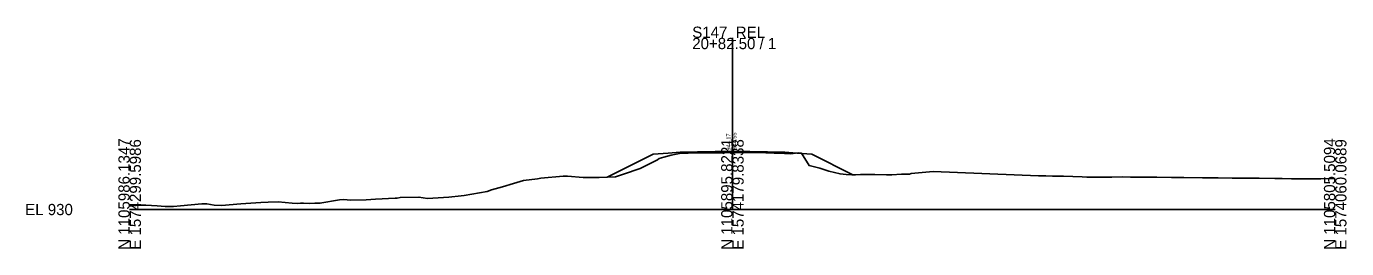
# Model space of a CAD drawing. Extents: x 1557985 to 1558314, y 1113650 to 1118205.
# Drawn here: x 1557985.4 to 1558314, y 1118150.1 to 1118205.3 of the extents above; entities that cross this region are included whole.
import ezdxf

# ---------------------------------------------------------------- set-up
doc = ezdxf.new("R2010")
doc.units = 0
for name, color, linetype in [('RD_GPK_XS_Cell', 7, 'Continuous'), ('RD_XS_EarthShd', 7, 'Continuous'), ('RD_XS_ExGround', 7, 'Continuous'), ('RD_XS_Pave', 7, 'Continuous'), ('RD_XS_TieSlope', 7, 'Continuous'), ('RD_XS_TX_Elev_EX', 7, 'Continuous'), ('RD_XS_TX_Elev_PR', 7, 'Continuous')]:
    doc.layers.add(name, color=color, linetype=linetype)

msp = doc.modelspace()

# ---------------------------------------------------------------- linework, layer by layer
at = {"layer": 'RD_GPK_XS_Cell'}
for p, q in [((1558161.13, 1118159.8), (1558161.13, 1118202.45)), ((1558011.13, 1118159.8), (1558161.13, 1118159.8)), ((1558161.13, 1118159.8), (1558311.13, 1118159.8))]:
    msp.add_line(p, q, dxfattribs=at)
at = {"layer": 'RD_XS_EarthShd'}
for p, q in [((1558145.13, 1118173.84), (1558141.38, 1118173.54)), ((1558148.13, 1118174.08), (1558145.13, 1118173.84)), ((1558174.13, 1118174.08), (1558177.13, 1118173.84)), ((1558177.13, 1118173.84), (1558180.88, 1118173.54))]:
    msp.add_line(p, q, dxfattribs=at)
at = {"layer": 'RD_XS_ExGround'}
msp.add_lwpolyline([(1558011.13, 1118160.72), (1558011.7, 1118160.75), (1558013.86, 1118160.91), (1558015.19, 1118160.85), (1558017.94, 1118160.7), (1558019.97, 1118160.57), (1558022.04, 1118160.58), (1558023.79, 1118160.74), (1558029.11, 1118161.19), (1558029.98, 1118161.25), (1558030.37, 1118161.18), (1558032.19, 1118160.86), (1558033.97, 1118160.79), (1558038.76, 1118161.2), (1558043.74, 1118161.54), (1558045.63, 1118161.6), (1558048.06, 1118161.72), (1558051.56, 1118161.38), (1558052.8, 1118161.31), (1558053.68, 1118161.35), (1558054.42, 1118161.42), (1558055.92, 1118161.32), (1558057.24, 1118161.37), (1558058.48, 1118161.34), (1558063.31, 1118162.18), (1558064.32, 1118162.28), (1558066.14, 1118162.1), (1558069.95, 1118162.21), (1558072.3, 1118162.4), (1558077.21, 1118162.6), (1558077.66, 1118162.59), (1558078.43, 1118162.77), (1558083.13, 1118162.9), (1558085.22, 1118162.54), (1558090.54, 1118162.91), (1558093.66, 1118163.22), (1558094.39, 1118163.31), (1558100.07, 1118164.32), (1558101.21, 1118164.67), (1558103.87, 1118165.44), (1558106.62, 1118166.27), (1558109.14, 1118167.01), (1558112.6, 1118167.44), (1558113.48, 1118167.56), (1558119.01, 1118168.07), (1558119.52, 1118168.07), (1558120.08, 1118168.07), (1558123.95, 1118167.73), (1558127.39, 1118167.76), (1558127.95, 1118167.78), (1558132.01, 1118167.92), (1558134, 1118168.6), (1558138.18, 1118170.01), (1558142.46, 1118172.14), (1558142.86, 1118172.48), (1558144.05, 1118172.82), (1558145.86, 1118173.3), (1558147.94, 1118173.75), (1558152.33, 1118173.88), (1558154.57, 1118173.89), (1558157.05, 1118173.88), (1558159.21, 1118173.92), (1558159.85, 1118173.93), (1558161.13, 1118173.97), (1558162.9, 1118174.01), (1558163.6, 1118174), (1558164.54, 1118173.96), (1558167.98, 1118173.93), (1558169.45, 1118173.92), (1558170.16, 1118173.89), (1558171.51, 1118173.82), (1558172.36, 1118173.8), (1558173.6, 1118173.78), (1558174.11, 1118173.76), (1558175.61, 1118173.67), (1558177.52, 1118173.89), (1558178.33, 1118173.78), (1558180.21, 1118170.71), (1558180.55, 1118170.66), (1558182.9, 1118170.1), (1558185.09, 1118169.35), (1558187.9, 1118168.65), (1558189.42, 1118168.49), (1558190.87, 1118168.44), (1558191.76, 1118168.45), (1558193.03, 1118168.5), (1558194.16, 1118168.53), (1558195.04, 1118168.51), (1558196.59, 1118168.48), (1558199.5, 1118168.42), (1558200.82, 1118168.42), (1558203.24, 1118168.59), (1558205.17, 1118168.57), (1558205.63, 1118168.75), (1558211.07, 1118169.28), (1558237.33, 1118168.21), (1558239.09, 1118168.18), (1558240.77, 1118168.05), (1558242.33, 1118168.09), (1558243.52, 1118168.09), (1558248.2, 1118167.91), (1558249.3, 1118167.86), (1558249.89, 1118167.85), (1558250.36, 1118167.86), (1558251.81, 1118167.86), (1558254.77, 1118167.88), (1558255.53, 1118167.88), (1558258.21, 1118167.89), (1558260.18, 1118167.84), (1558260.9, 1118167.83), (1558261.29, 1118167.83), (1558264.9, 1118167.81), (1558266.04, 1118167.8), (1558266.78, 1118167.8), (1558270.4, 1118167.73), (1558271.03, 1118167.73), (1558273.45, 1118167.73), (1558278.1, 1118167.66), (1558278.46, 1118167.64), (1558280.11, 1118167.65), (1558280.8, 1118167.65), (1558282.04, 1118167.64), (1558285.5, 1118167.59), (1558287.89, 1118167.57), (1558288.3, 1118167.56), (1558289.82, 1118167.6), (1558291.23, 1118167.58), (1558292.24, 1118167.57), (1558296.08, 1118167.52), (1558296.54, 1118167.52), (1558297.94, 1118167.49), (1558300.22, 1118167.46), (1558302.94, 1118167.43), (1558305.69, 1118167.41), (1558307.58, 1118167.43), (1558309.97, 1118167.5), (1558310.52, 1118167.51), (1558311.13, 1118167.53)], dxfattribs=at)
at = {"layer": 'RD_XS_Pave'}
for p, q in [((1558161.13, 1118174.34), (1558148.13, 1118174.08)), ((1558174.13, 1118174.08), (1558161.13, 1118174.34))]:
    msp.add_line(p, q, dxfattribs=at)
at = {"layer": 'RD_XS_TieSlope'}
for p, q in [((1558141.38, 1118173.54), (1558129.98, 1118167.85)), ((1558180.88, 1118173.54), (1558191.09, 1118168.44))]:
    msp.add_line(p, q, dxfattribs=at)

# ---------------------------------------------------------------- texts
at = {"layer": 'RD_GPK_XS_Cell'}
for s, p in [('S147_REL', (1558151.13, 1118202.45)), ('20+82.50 / 1', (1558151.13, 1118199.65)), ('EL 930', (1557985.13, 1118158.4))]:
    msp.add_text(s, height=2.8, dxfattribs=at).set_placement(p)
for s, p in [('N 1105986.1347', (1558011.13, 1118149.8)), ('N 1105895.8221', (1558161.13, 1118149.8)), ('N 1105805.5094', (1558311.13, 1118149.8)), ('E 1574299.5986', (1558013.93, 1118149.8)), ('E 1574179.8338', (1558163.93, 1118149.8)), ('E 1574060.0689', (1558313.93, 1118149.8))]:
    msp.add_text(s, height=2.8, rotation=90, dxfattribs=at).set_placement(p)
at = {"layer": 'RD_XS_TX_Elev_EX'}
msp.add_text('944.17', height=1, rotation=90, dxfattribs=at).set_placement((1558160.63, 1118174.47))
at = {"layer": 'RD_XS_TX_Elev_PR'}
msp.add_text(' 944.55', height=1, rotation=90, dxfattribs=at).set_placement((1558162.13, 1118174.34))

doc.saveas('drawing.dxf')
